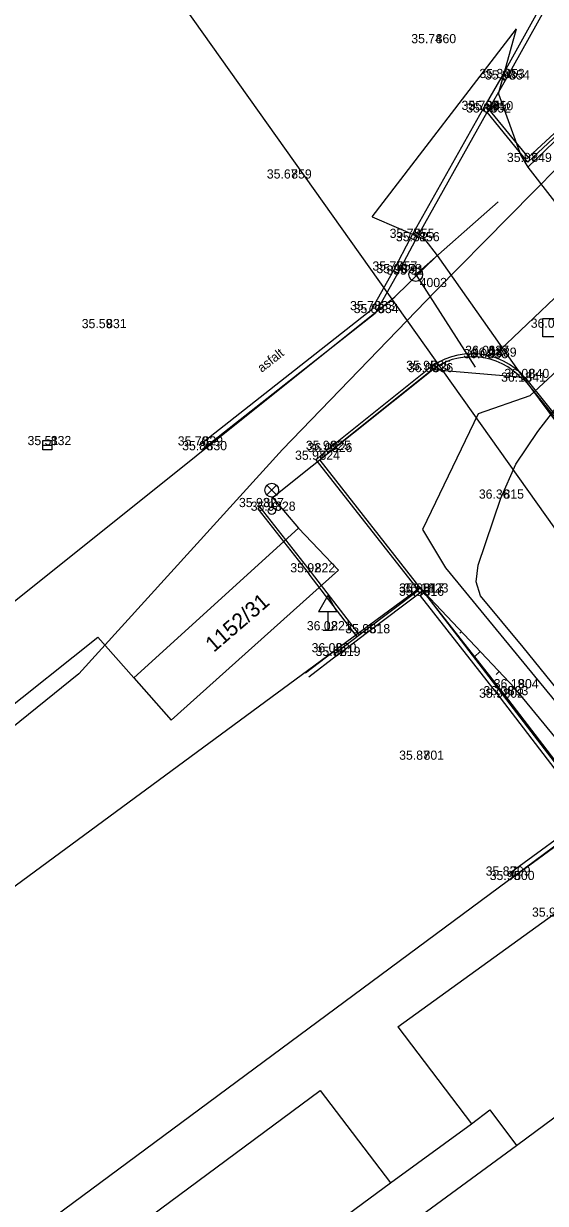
# Model space of a CAD drawing. Extents: x -609709 to -609357, y -1051535 to -1051131.
# Drawn here: x -609637.29 to -609623.05, y -1051300.14 to -1051267.96 of the extents above; entities that cross this region are included whole.
import ezdxf

# ---------------------------------------------------------------- set-up
doc = ezdxf.new("R2010")
doc.units = 0
for name, color, linetype in [('Vrstva 1', 7, 'Continuous'), ('Vrstva 10', 7, 'Continuous'), ('Vrstva 12', 7, 'Continuous'), ('Vrstva 15', 7, 'Continuous'), ('Vrstva 17', 7, 'Continuous'), ('Vrstva 18', 7, 'Continuous'), ('Vrstva 2', 7, 'Continuous'), ('Vrstva 3', 7, 'Continuous'), ('Vrstva 4', 7, 'Continuous'), ('Vrstva 5', 7, 'Continuous'), ('Vrstva 6', 7, 'Continuous'), ('Vrstva 8', 7, 'Continuous')]:
    doc.layers.add(name, color=color, linetype=linetype)

msp = doc.modelspace()

# ---------------------------------------------------------------- linework, layer by layer
at = {"layer": 'Vrstva 1'}
for p, q in [((-609626.14, -1051268.5), (-609626.14, -1051268.5)), ((-609624.27, -1051269.45), (-609624.27, -1051269.45)), ((-609624.13, -1051269.49), (-609624.13, -1051269.49)), ((-609624.77, -1051270.32), (-609624.77, -1051270.32)), ((-609624.64, -1051270.39), (-609624.64, -1051270.39)), ((-609624.58, -1051270.33), (-609624.58, -1051270.33)), ((-609623.53, -1051271.74), (-609623.53, -1051271.74)), ((-609630.08, -1051272.19), (-609630.08, -1051272.19)), ((-609626.73, -1051273.81), (-609626.73, -1051273.81)), ((-609626.59, -1051273.9), (-609626.59, -1051273.9)), ((-609627.2, -1051274.7), (-609627.2, -1051274.7)), ((-609627.08, -1051274.77), (-609627.08, -1051274.77)), ((-609626.59, -1051274.81), (-609626.59, -1051274.81)), ((-609627.81, -1051275.78), (-609627.81, -1051275.78)), ((-609627.71, -1051275.86), (-609627.71, -1051275.86)), ((-609635.13, -1051276.27), (-609635.13, -1051276.27)), ((-609624.72, -1051277.09), (-609624.72, -1051277.09)), ((-609624.7, -1051277), (-609624.7, -1051277)), ((-609624.49, -1051277.05), (-609624.49, -1051277.05)), ((-609626.28, -1051277.41), (-609626.28, -1051277.41)), ((-609626.22, -1051277.47), (-609626.22, -1051277.47)), ((-609623.69, -1051277.73), (-609623.69, -1051277.73)), ((-609623.6, -1051277.63), (-609623.6, -1051277.63)), ((-609636.64, -1051279.46), (-609636.64, -1051279.46)), ((-609632.5, -1051279.47), (-609632.5, -1051279.47)), ((-609632.39, -1051279.6), (-609632.39, -1051279.6)), ((-609629.01, -1051279.59), (-609629.01, -1051279.59)), ((-609628.97, -1051279.65), (-609628.97, -1051279.65)), ((-609629.31, -1051279.86), (-609629.31, -1051279.86)), ((-609624.29, -1051280.92), (-609624.29, -1051280.92)), ((-609630.84, -1051281.15), (-609630.84, -1051281.15)), ((-609630.52, -1051281.25), (-609630.52, -1051281.25)), ((-609629.44, -1051282.93), (-609629.44, -1051282.93)), ((-609626.47, -1051283.48), (-609626.47, -1051283.48)), ((-609626.47, -1051283.57), (-609626.47, -1051283.57)), ((-609626.35, -1051283.48), (-609626.35, -1051283.48)), ((-609628.99, -1051284.51), (-609628.99, -1051284.51)), ((-609627.94, -1051284.59), (-609627.94, -1051284.59)), ((-609628.86, -1051285.11), (-609628.86, -1051285.11)), ((-609628.75, -1051285.21), (-609628.75, -1051285.21)), ((-609623.89, -1051286.09), (-609623.89, -1051286.09)), ((-609624.29, -1051286.35), (-609624.29, -1051286.35)), ((-609624.17, -1051286.28), (-609624.17, -1051286.28)), ((-609626.47, -1051288.04), (-609626.47, -1051288.04)), ((-609624.11, -1051291.2), (-609624.11, -1051291.2)), ((-609624, -1051291.32), (-609624, -1051291.32))]:
    msp.add_line(p, q, dxfattribs=at)
at = {"layer": 'Vrstva 10'}
for p, q in [((-609623.53, -1051271.88), (-609592.58, -1051242.01)), ((-609627.78, -1051273.23), (-609623.84, -1051268.11)), ((-609624.33, -1051269.88), (-609623.84, -1051268.11)), ((-609624.33, -1051269.88), (-609623.72, -1051271.56)), ((-609623.72, -1051271.56), (-609623.53, -1051271.88)), ((-609623.53, -1051271.88), (-609622.18, -1051273.63)), ((-609627.78, -1051273.23), (-609626.34, -1051273.85)), ((-609626.34, -1051273.85), (-609626.01, -1051274.29)), ((-609627.16, -1051275.42), (-609626.01, -1051274.29)), ((-609626.01, -1051274.29), (-609623.67, -1051277.61)), ((-609645.37, -1051289.97), (-609627.16, -1051275.42)), ((-609630.5, -1051280.89), (-609626.12, -1051277.4)), ((-609626.12, -1051277.4), (-609623.67, -1051277.61)), ((-609623.67, -1051277.61), (-609605.63, -1051301.94)), ((-609630.5, -1051280.89), (-609629.79, -1051281.72)), ((-609634.28, -1051285.81), (-609629.79, -1051281.72)), ((-609629.79, -1051281.72), (-609628.7, -1051282.87)), ((-609633.26, -1051286.96), (-609628.7, -1051282.87)), ((-609673.93, -1051318.27), (-609626.47, -1051283.34)), ((-609626.47, -1051283.34), (-609621.69, -1051289.57)), ((-609644.29, -1051291.87), (-609635.26, -1051284.7)), ((-609635.26, -1051284.7), (-609634.28, -1051285.81)), ((-609634.28, -1051285.81), (-609633.26, -1051286.96)), ((-609672.03, -1051326.83), (-609621.69, -1051289.57)), ((-609627.08, -1051295.32), (-609620.72, -1051290.73)), ((-609623.84, -1051298.56), (-609618.08, -1051294.28)), ((-609627.08, -1051295.32), (-609625.07, -1051297.97)), ((-609641.4, -1051306.08), (-609629.2, -1051297.06)), ((-609629.2, -1051297.06), (-609627.28, -1051299.58)), ((-609625.07, -1051297.97), (-609624.57, -1051297.59)), ((-609624.57, -1051297.59), (-609623.84, -1051298.56)), ((-609627.28, -1051299.58), (-609625.07, -1051297.97)), ((-609630.01, -1051303.07), (-609623.84, -1051298.56)), ((-609630.72, -1051302.11), (-609627.28, -1051299.58))]:
    msp.add_line(p, q, dxfattribs=at)
at = {"layer": 'Vrstva 12'}
msp.add_lwpolyline([(-609644.336, -1051251.436), (-609604.801, -1051307.048), (-609620.698, -1051318.606), (-609619.426, -1051320.272)], dxfattribs=at)
at = {"layer": 'Vrstva 15'}
for points in [[(-609592.54, -1051249), (-609597.09, -1051253.54), (-609603.86, -1051260.31), (-609608.84, -1051264.59), (-609616.08, -1051271.44), (-609620.11, -1051274.18), (-609621.01, -1051275.83), (-609623.48, -1051278.12), (-609624.89, -1051278.61), (-609626.41, -1051281.76), (-609625.78, -1051282.81), (-609616.94, -1051293.56), (-609613.57, -1051297.39), (-609614.852, -1051298.693)], [(-609615.07, -1051296.33), (-609615.78, -1051295.09), (-609620.45, -1051288.93), (-609623.66, -1051284.97), (-609624.82, -1051283.57), (-609624.94, -1051283.19), (-609624.89, -1051282.73), (-609624.27, -1051280.91), (-609623.86, -1051279.98), (-609623.26, -1051279.09), (-609620.52, -1051275.54), (-609620, -1051274.23), (-609619.55, -1051273.31), (-609618.56, -1051272.15), (-609610.34, -1051264.5)]]:
    msp.add_lwpolyline(points, dxfattribs=at)
at = {"layer": 'Vrstva 17'}
msp.add_lwpolyline([(-609531.786, -1051180.515), (-609532.61, -1051181.07), (-609528.54, -1051185.58), (-609545.95, -1051201.69), (-609546.72, -1051202.27), (-609551.04, -1051206.15), (-609565.42, -1051219.63), (-609579.77, -1051233.3), (-609583.56, -1051235.84), (-609591.75, -1051241.92), (-609609.05, -1051258.52), (-609618.01, -1051267.11), (-609626.05, -1051275.26), (-609630.23, -1051279.58), (-609635.78, -1051285.7), (-609642.85, -1051291.4), (-609672.95, -1051307.23)], dxfattribs=at)
at = {"layer": 'Vrstva 18'}
for points in [[(-609626.59, -1051274.81), (-609624.34, -1051272.825)], [(-609626.59, -1051274.81), (-609624.971, -1051277.336)]]:
    msp.add_lwpolyline(points, dxfattribs=at)
for radius in [0.188, 0.025]:
    msp.add_circle((-609626.59, -1051274.81), radius, dxfattribs=at)
at = {"layer": 'Vrstva 4'}
for p, q in [((-609621.229, -1051269.489), (-609623.519, -1051271.62)), ((-609628.958, -1051279.651), (-609626.23, -1051277.472)), ((-609623.638, -1051277.663), (-609622.489, -1051279.091)), ((-609629.201, -1051279.869), (-609628.958, -1051279.651)), ((-609626.407, -1051283.431), (-609629.201, -1051279.869)), ((-609630.903, -1051281.199), (-609629.503, -1051282.979)), ((-609629.504, -1051282.979), (-609628.197, -1051284.686))]:
    msp.add_line(p, q, dxfattribs=at)
for points in [[(-609602.18, -1051251.07), (-609605.07, -1051253.83), (-609609.18, -1051257.81), (-609614.3, -1051258.05), (-609615.05, -1051258.25), (-609617.76, -1051260.87), (-609618.44, -1051261.52), (-609620.65, -1051263.68), (-609621.37, -1051264.36), (-609621.71, -1051264.87), (-609623.18, -1051267.49), (-609624.27, -1051269.45), (-609624.77, -1051270.32), (-609626.73, -1051273.81), (-609627.2, -1051274.7), (-609627.81, -1051275.78), (-609632.5, -1051279.47)], [(-609602.083, -1051251.171), (-609604.973, -1051253.931), (-609609.121, -1051257.947), (-609614.278, -1051258.189), (-609614.979, -1051258.376), (-609617.663, -1051260.971), (-609618.343, -1051261.621), (-609620.553, -1051263.781), (-609621.262, -1051264.451), (-609621.591, -1051264.943), (-609623.058, -1051267.558), (-609624.148, -1051269.519), (-609624.648, -1051270.389), (-609626.607, -1051273.877), (-609627.077, -1051274.767), (-609627.702, -1051275.873), (-609632.413, -1051279.58)], [(-609624.27, -1051269.45), (-609624.148, -1051269.519)], [(-609621.175, -1051269.548), (-609623.53, -1051271.74)], [(-609624.77, -1051270.32), (-609624.648, -1051270.389)], [(-609623.53, -1051271.74), (-609624.645, -1051270.384)], [(-609624.6, -1051270.305), (-609623.519, -1051271.62)], [(-609626.73, -1051273.81), (-609626.607, -1051273.877)], [(-609621.68, -1051274.38), (-609624.49, -1051277.05)], [(-609627.2, -1051274.7), (-609627.077, -1051274.767)], [(-609629.01, -1051279.59), (-609626.28, -1051277.41)], [(-609623.6, -1051277.63), (-609623.66, -1051277.682)], [(-609623.6, -1051277.63), (-609622.45, -1051279.06)], [(-609629.31, -1051279.86), (-609629.01, -1051279.59)], [(-609626.519, -1051283.417), (-609629.31, -1051279.86)], [(-609630.84, -1051281.15), (-609630.903, -1051281.199)], [(-609630.84, -1051281.15), (-609629.44, -1051282.93)], [(-609629.44, -1051282.93), (-609628.133, -1051284.637)], [(-609628.799, -1051285.146), (-609627.988, -1051284.526), (-609626.519, -1051283.417)], [(-609628.75, -1051285.21), (-609627.94, -1051284.59), (-609626.406, -1051283.432)], [(-609626.358, -1051283.486), (-609626.47, -1051283.57), (-609624.29, -1051286.35), (-609621.84, -1051289.54), (-609624.11, -1051291.2)], [(-609626.358, -1051283.486), (-609624.179, -1051286.264), (-609621.642, -1051289.568), (-609624.027, -1051291.313)], [(-609627.94, -1051284.59), (-609627.988, -1051284.526)], [(-609628.839, -1051285.094), (-609629.599, -1051285.676)], [(-609628.75, -1051285.21), (-609629.51, -1051285.792)], [(-609628.75, -1051285.21), (-609628.839, -1051285.094)]]:
    msp.add_lwpolyline(points, dxfattribs=at)
for radius, end in [(1.923, 129.6551), (1.843, 129.6776)]:
    msp.add_arc((-609625.053, -1051278.891), radius, 40.9592, end, dxfattribs=at)
at = {"layer": 'Vrstva 5'}
for p, q in [((-609636.765, -1051279.46), (-609636.515, -1051279.46)), ((-609630.652, -1051280.82), (-609630.388, -1051280.555)), ((-609630.652, -1051280.555), (-609630.388, -1051280.82)), ((-609630.52, -1051280.875), (-609630.52, -1051281.15)), ((-609628.99, -1051283.56), (-609629.24, -1051284.01)), ((-609628.99, -1051283.56), (-609628.74, -1051284.01)), ((-609628.74, -1051284.01), (-609629.24, -1051284.01)), ((-609628.99, -1051284.01), (-609628.99, -1051284.51)), ((-609629.115, -1051284.51), (-609628.865, -1051284.51))]:
    msp.add_line(p, q, dxfattribs=at)
for points in [[(-609623.12, -1051276.01), (-609622.62, -1051276.01), (-609622.62, -1051276.51), (-609623.12, -1051276.51)], [(-609636.765, -1051279.335), (-609636.515, -1051279.335), (-609636.515, -1051279.585), (-609636.765, -1051279.585)]]:
    msp.add_lwpolyline(points, close=True, dxfattribs=at)
for centre, radius in [((-609630.52, -1051280.688), 0.188), ((-609630.52, -1051281.25), 0.1)]:
    msp.add_circle(centre, radius, dxfattribs=at)
at = {"layer": 'Vrstva 6'}
msp.add_lwpolyline([(-609622.44, -1051292.85), (-609620.06, -1051290.7), (-609621.32, -1051289.21), (-609623.89, -1051286.09), (-609626.35, -1051283.48)], dxfattribs=at)
at = {"layer": 'Vrstva 8'}
for p, q in [((-609625.346, -1051284.545), (-609625.388, -1051284.584)), ((-609624.832, -1051285.091), (-609624.986, -1051285.236)), ((-609624.317, -1051285.637), (-609624.399, -1051285.713))]:
    msp.add_line(p, q, dxfattribs=at)

# ---------------------------------------------------------------- texts
at = {"layer": 'Vrstva 10'}
msp.add_text('1152/31', height=0.425, rotation=40.7412, dxfattribs=at).set_placement((-609632.102, -1051285.128))
at = {"layer": 'Vrstva 18'}
msp.add_text(' 4003', height=0.25, dxfattribs=at).set_placement((-609626.576, -1051275.15))
at = {"layer": 'Vrstva 2'}
for s, p in [(' 860', (-609626.14, -1051268.5)), (' 853', (-609624.27, -1051269.45)), (' 854', (-609624.13, -1051269.49)), (' 851', (-609624.77, -1051270.32)), (' 850', (-609624.58, -1051270.33)), (' 852', (-609624.64, -1051270.39)), (' 849', (-609623.53, -1051271.74)), (' 859', (-609630.08, -1051272.19)), (' 855', (-609626.73, -1051273.81)), (' 856', (-609626.59, -1051273.9)), (' 857', (-609627.2, -1051274.7)), (' 858', (-609627.08, -1051274.77)), (' 833', (-609627.81, -1051275.78)), (' 834', (-609627.71, -1051275.86)), (' 831', (-609635.13, -1051276.27)), (' 838', (-609624.72, -1051277.09)), (' 837', (-609624.7, -1051277)), (' 839', (-609624.49, -1051277.05)), (' 835', (-609626.28, -1051277.41)), (' 836', (-609626.22, -1051277.47)), (' 841', (-609623.69, -1051277.73)), (' 840', (-609623.6, -1051277.63)), (' 832', (-609636.64, -1051279.46)), (' 829', (-609632.5, -1051279.47)), (' 830', (-609632.39, -1051279.6)), (' 825', (-609629.01, -1051279.59)), (' 826', (-609628.97, -1051279.65)), (' 824', (-609629.31, -1051279.86)), (' 815', (-609624.29, -1051280.92)), (' 827', (-609630.84, -1051281.15)), (' 828', (-609630.52, -1051281.25)), (' 822', (-609629.44, -1051282.93)), (' 817', (-609626.47, -1051283.48)), (' 823', (-609626.35, -1051283.48)), (' 816', (-609626.47, -1051283.57)), (' 821', (-609628.99, -1051284.51)), (' 818', (-609627.94, -1051284.59)), (' 820', (-609628.86, -1051285.11)), (' 819', (-609628.75, -1051285.21)), (' 804', (-609623.89, -1051286.09)), (' 802', (-609624.29, -1051286.35)), (' 803', (-609624.17, -1051286.28)), (' 801', (-609626.47, -1051288.04)), (' 799', (-609624.11, -1051291.2)), (' 800', (-609624, -1051291.32))]:
    msp.add_text(s, height=0.25, dxfattribs=at).set_placement(p)
at = {"layer": 'Vrstva 3'}
for s, p in [('35.74', (-609626.713, -1051268.5)), ('35.80', (-609624.853, -1051269.45)), ('35.93', (-609624.703, -1051269.49)), ('35.79', (-609625.343, -1051270.32)), ('35.84', (-609625.153, -1051270.33)), ('35.84', (-609625.213, -1051270.39)), ('35.97', (-609624.103, -1051271.74)), ('35.67', (-609630.653, -1051272.19)), ('35.77', (-609627.303, -1051273.81)), ('35.81', (-609627.132, -1051273.9)), ('35.77', (-609627.773, -1051274.7)), ('35.90', (-609627.663, -1051274.77)), ('335.91', (-609627.39, -1051274.81)), ('35.78', (-609628.383, -1051275.78)), ('35.89', (-609628.283, -1051275.86)), ('35.59', (-609635.703, -1051276.27)), ('36.00', (-609623.453, -1051276.26)), ('36.08', (-609625.293, -1051277.09)), ('36.01', (-609625.242, -1051277)), ('36.03', (-609625.063, -1051277.05)), ('35.95', (-609626.853, -1051277.41)), ('36.00', (-609626.803, -1051277.47)), ('36.13', (-609624.263, -1051277.73)), ('36.08', (-609624.173, -1051277.63)), ('35.51', (-609637.182, -1051279.46)), ('35.70', (-609633.083, -1051279.47)), ('35.88', (-609632.963, -1051279.6)), ('35.96', (-609629.589, -1051279.59)), ('36.03', (-609629.543, -1051279.65)), ('35.97', (-609629.883, -1051279.86)), ('36.36', (-609624.869, -1051280.92)), ('35.93', (-609631.413, -1051281.15)), ('35.93', (-609631.093, -1051281.25)), ('35.92', (-609630.013, -1051282.93)), ('35.98', (-609627.043, -1051283.48)), ('36.14', (-609626.923, -1051283.48)), ('35.96', (-609627.049, -1051283.57)), ('36.02', (-609629.563, -1051284.51)), ('35.95', (-609628.513, -1051284.59)), ('36.08', (-609629.433, -1051285.11)), ('35.92', (-609629.323, -1051285.21)), ('36.19', (-609624.463, -1051286.09)), ('35.92', (-609624.863, -1051286.35)), ('36.08', (-609624.743, -1051286.28)), ('35.87', (-609627.043, -1051288.04)), ('35.82', (-609624.683, -1051291.2)), ('35.95', (-609624.573, -1051291.32)), ('35.96', (-609623.419, -1051292.32))]:
    msp.add_text(s, height=0.25, dxfattribs=at).set_placement(p)
at = {"layer": 'Vrstva 4'}
msp.add_text('asfalt', height=0.25, rotation=38.195, dxfattribs=at).set_placement((-609630.791, -1051277.49))

doc.saveas('drawing.dxf')
